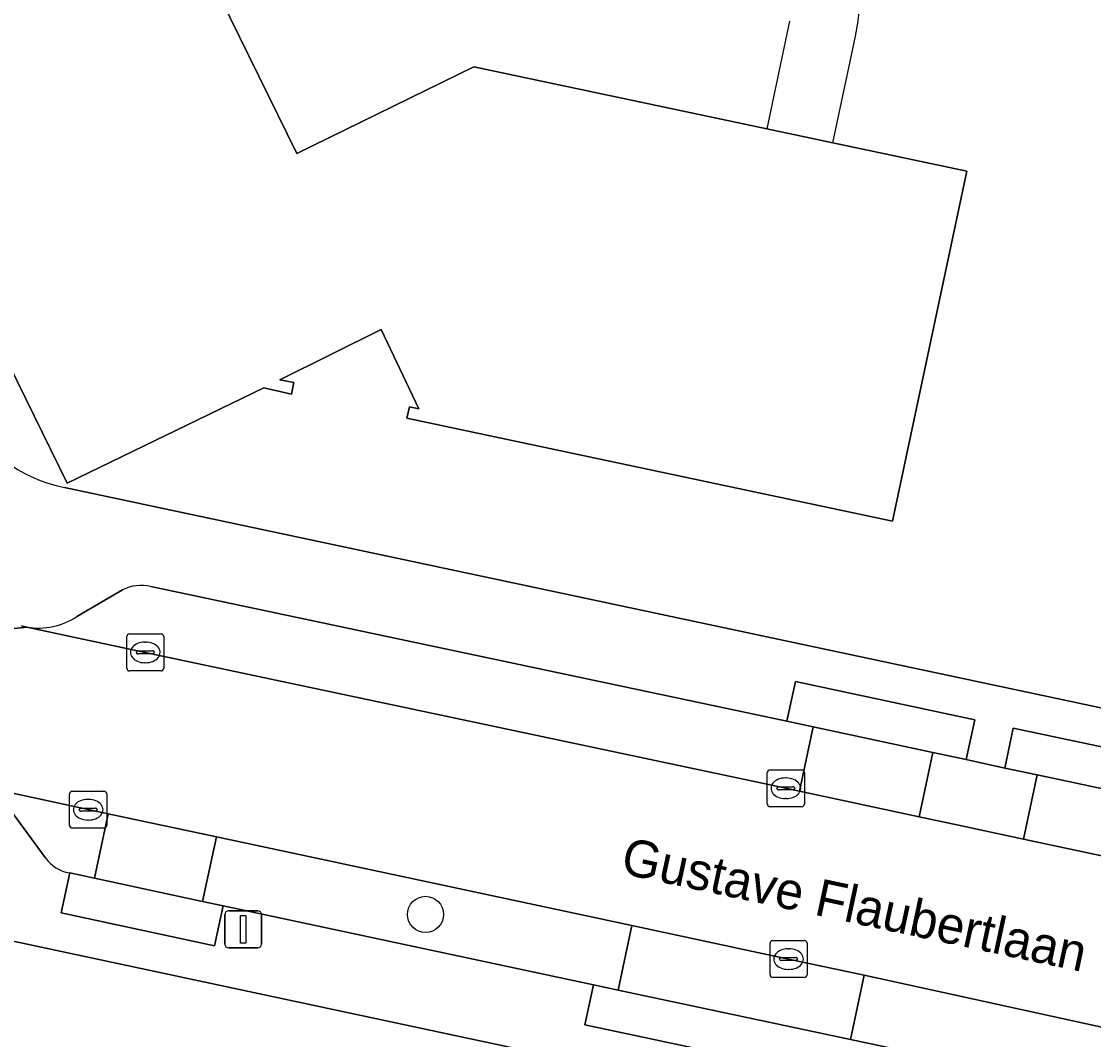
# Model space of a CAD drawing. Extents: x 160455 to 162082, y 388339 to 389736.
# Drawn here: x 160758.44 to 160787.43, y 389012.07 to 389039.61 of the extents above; entities that cross this region are included whole.
import ezdxf

# ---------------------------------------------------------------- set-up
doc = ezdxf.new("R2010")
doc.units = 0
for name, color, linetype in [('IMGEO_Boom', 7, 'Continuous'), ('IMGEO_Erf', 7, 'Continuous'), ('IMGEO_Kolk', 7, 'Continuous'), ('IMGEO_Lichtmast', 7, 'Continuous'), ('IMGEO_Openbare_ruimte_label', 7, 'Continuous'), ('IMGEO_Pand', 7, 'Continuous'), ('IMGEO_Pand_overbouw', 7, 'Continuous'), ('IMGEO_Parkeervlak_open', 7, 'Continuous'), ('IMGEO_Rijbaan_lokaal_gesloten', 7, 'Continuous'), ('IMGEO_Voetpad_open', 7, 'Continuous')]:
    doc.layers.add(name, color=color, linetype=linetype)

msp = doc.modelspace()

# ---------------------------------------------------------------- linework, layer by layer
at = {"layer": 'IMGEO_Boom'}
msp.add_circle((160769.368, 389015.453), 0.489, dxfattribs=at)
at = {"layer": 'IMGEO_Erf'}
for points in [[(160762.799, 389042.336), (160765.888, 389036.033), (160770.678, 389038.374), (160778.592, 389036.698), (160780.379, 389036.32), (160783.999, 389035.553), (160781.995, 389026.092), (160768.864, 389028.873), (160768.937, 389029.183), (160769.19, 389029.124), (160768.172, 389031.272), (160765.432, 389029.914), (160765.805, 389029.841), (160765.743, 389029.525), (160765, 389029.692), (160759.677, 389027.119), (160750.279, 389046.295)], [(160759.604, 389027.003), (160851.028, 389007.553), (160853.401, 389018.708), (160853.658, 389018.653), (160854.144, 389020.941), (160857.076, 389020.317), (160856.589, 389018.03), (160856.015, 389015.332), (160857.131, 389015.095), (160855.333, 389006.643), (160876.381, 389002.172), (160884.301, 389000.512)], [(160816.292, 389002.325), (160756.984, 389014.991)]]:
    msp.add_lwpolyline(points, dxfattribs=at)
msp.add_arc((160760.329, 389030.768), 3.835, 205.0795, 259.1013, dxfattribs=at)
at = {"layer": 'IMGEO_Kolk'}
for p, q in [((160761.291, 389022.113), (160761.291, 389022.965)), ((160761.366, 389023.039), (160762.218, 389023.039)), ((160762.292, 389022.965), (160762.292, 389022.113)), ((160761.55, 389022.533), (160761.55, 389022.545)), ((160761.593, 389022.582), (160761.991, 389022.582)), ((160761.779, 389022.819), (160761.804, 389022.819)), ((160762.034, 389022.545), (160762.034, 389022.533)), ((160761.988, 389022.496), (160761.59, 389022.496)), ((160761.802, 389022.259), (160761.777, 389022.259)), ((160762.218, 389022.039), (160761.366, 389022.039)), ((160778.683, 389019.363), (160779.535, 389019.363)), ((160778.608, 389018.437), (160778.608, 389019.289)), ((160779.096, 389019.143), (160779.121, 389019.143)), ((160779.609, 389019.289), (160779.609, 389018.437)), ((160759.822, 389018.785), (160760.674, 389018.785)), ((160778.867, 389018.857), (160778.867, 389018.869)), ((160779.305, 389018.82), (160778.907, 389018.82)), ((160778.91, 389018.906), (160779.308, 389018.906)), ((160779.351, 389018.869), (160779.351, 389018.857)), ((160759.747, 389017.859), (160759.747, 389018.711)), ((160760.235, 389018.565), (160760.26, 389018.565)), ((160760.748, 389018.711), (160760.748, 389017.859)), ((160779.119, 389018.583), (160779.094, 389018.583)), ((160760.006, 389018.279), (160760.006, 389018.291)), ((160760.444, 389018.242), (160760.046, 389018.242)), ((160760.049, 389018.328), (160760.447, 389018.328)), ((160760.49, 389018.291), (160760.49, 389018.279)), ((160779.535, 389018.363), (160778.683, 389018.363)), ((160760.258, 389018.005), (160760.233, 389018.005)), ((160760.674, 389017.785), (160759.822, 389017.785)), ((160778.756, 389014.745), (160779.608, 389014.745)), ((160778.681, 389013.819), (160778.681, 389014.671)), ((160779.169, 389014.525), (160779.194, 389014.525)), ((160779.682, 389014.671), (160779.682, 389013.819)), ((160778.94, 389014.239), (160778.94, 389014.251)), ((160779.378, 389014.202), (160778.98, 389014.202)), ((160778.983, 389014.288), (160779.381, 389014.288)), ((160779.424, 389014.251), (160779.424, 389014.239)), ((160779.192, 389013.965), (160779.167, 389013.965)), ((160779.608, 389013.745), (160778.756, 389013.745))]:
    msp.add_line(p, q, dxfattribs=at)
for points in [[(160761.291, 389022.113), (160761.291, 389022.965)], [(160761.366, 389023.039), (160762.218, 389023.039)], [(160762.292, 389022.965), (160762.292, 389022.113)], [(160762.218, 389022.039), (160761.366, 389022.039)], [(160778.683, 389019.363), (160779.535, 389019.363)], [(160778.608, 389018.437), (160778.608, 389019.289)], [(160779.609, 389019.289), (160779.609, 389018.437)], [(160759.822, 389018.785), (160760.674, 389018.785)], [(160759.747, 389017.859), (160759.747, 389018.711)], [(160760.748, 389018.711), (160760.748, 389017.859)], [(160779.535, 389018.363), (160778.683, 389018.363)], [(160760.674, 389017.785), (160759.822, 389017.785)], [(160778.756, 389014.745), (160779.608, 389014.745)], [(160778.681, 389013.819), (160778.681, 389014.671)], [(160779.682, 389014.671), (160779.682, 389013.819)], [(160779.608, 389013.745), (160778.756, 389013.745)]]:
    msp.add_lwpolyline(points, dxfattribs=at)
for centre, radius, start, end in [((160761.368, 389022.963), 0.0765, 91.552, 178.448), ((160761.368, 389022.963), 0.0765, 91.552, 178.448), ((160762.216, 389022.963), 0.0765, 1.552, 88.448), ((160762.216, 389022.963), 0.0765, 1.552, 88.448), ((160761.59, 389022.542), 0.0403, 85.8775, 175.7526), ((160761.587, 389022.532), 0.0366, 178.938, 274.7102), ((160761.991, 389022.539), 0.043, 264.8664, 352.4533), ((160761.995, 389022.544), 0.0386, 1.7309, 96.639), ((160761.368, 389022.115), 0.0765, 181.552, 268.448), ((160761.368, 389022.115), 0.0765, 181.552, 268.448), ((160762.216, 389022.115), 0.0765, 271.552, 358.448), ((160762.216, 389022.115), 0.0765, 271.552, 358.448), ((160778.685, 389019.287), 0.0765, 91.552, 178.448), ((160778.685, 389019.287), 0.0765, 91.552, 178.448), ((160779.533, 389019.287), 0.0765, 1.552, 88.448), ((160779.533, 389019.287), 0.0765, 1.552, 88.448), ((160759.824, 389018.709), 0.0765, 91.552, 178.448), ((160759.824, 389018.709), 0.0765, 91.552, 178.448), ((160760.672, 389018.709), 0.0765, 1.552, 88.448), ((160760.672, 389018.709), 0.0765, 1.552, 88.448), ((160778.907, 389018.866), 0.0403, 85.8775, 175.7526), ((160778.904, 389018.856), 0.0366, 178.938, 274.7102), ((160779.308, 389018.863), 0.043, 264.8664, 352.4533), ((160779.312, 389018.868), 0.0386, 1.7309, 96.639), ((160760.046, 389018.288), 0.0403, 85.8775, 175.7526), ((160760.043, 389018.278), 0.0366, 178.938, 274.7102), ((160760.447, 389018.285), 0.043, 264.8664, 352.4533), ((160760.451, 389018.29), 0.0386, 1.7309, 96.639), ((160778.685, 389018.439), 0.0765, 181.552, 268.448), ((160778.685, 389018.439), 0.0765, 181.552, 268.448), ((160779.533, 389018.439), 0.0765, 271.552, 358.448), ((160779.533, 389018.439), 0.0765, 271.552, 358.448), ((160759.824, 389017.861), 0.0765, 181.552, 268.448), ((160759.824, 389017.861), 0.0765, 181.552, 268.448), ((160760.672, 389017.861), 0.0765, 271.552, 358.448), ((160760.672, 389017.861), 0.0765, 271.552, 358.448), ((160778.758, 389014.669), 0.0765, 91.552, 178.448), ((160778.758, 389014.669), 0.0765, 91.552, 178.448), ((160779.606, 389014.669), 0.0765, 1.552, 88.448), ((160779.606, 389014.669), 0.0765, 1.552, 88.448), ((160778.98, 389014.248), 0.0403, 85.8775, 175.7526), ((160778.977, 389014.238), 0.0366, 178.938, 274.7102), ((160779.381, 389014.245), 0.043, 264.8664, 352.4533), ((160779.385, 389014.25), 0.0386, 1.7309, 96.639), ((160778.758, 389013.821), 0.0765, 181.552, 268.448), ((160778.758, 389013.821), 0.0765, 181.552, 268.448), ((160779.606, 389013.821), 0.0765, 271.552, 358.448), ((160779.606, 389013.821), 0.0765, 271.552, 358.448)]:
    msp.add_arc(centre, radius, start, end, dxfattribs=at)
for centre, major_axis, ratio, start_param, end_param in [((160761.778, 389022.539), (-0.387, 0.002), 0.722429, 4.712389, 7.853982), ((160761.803, 389022.539), (-0.39, 0.002), 0.717154, 1.570796, 4.712389), ((160779.095, 389018.863), (-0.387, 0.002), 0.722429, 4.712389, 7.853982), ((160779.12, 389018.863), (-0.39, 0.002), 0.717154, 1.570796, 4.712389), ((160760.234, 389018.285), (-0.387, 0.002), 0.722429, 4.712389, 7.853982), ((160760.259, 389018.285), (-0.39, 0.002), 0.717154, 1.570796, 4.712389), ((160779.168, 389014.245), (-0.387, 0.002), 0.722429, 4.712389, 7.853982), ((160779.193, 389014.245), (-0.39, 0.002), 0.717154, 1.570796, 4.712389)]:
    msp.add_ellipse(centre, major_axis=major_axis, ratio=ratio, start_param=start_param, end_param=end_param, dxfattribs=at)
at = {"layer": 'IMGEO_Lichtmast'}
for p, q in [((160763.944, 389014.647), (160763.944, 389015.447)), ((160763.944, 389015.447), (160763.944, 389014.647)), ((160764.044, 389015.547), (160764.834, 389015.547)), ((160764.834, 389015.547), (160764.044, 389015.547)), ((160764.934, 389015.447), (160764.934, 389014.647)), ((160764.934, 389014.647), (160764.934, 389015.447)), ((160764.834, 389014.547), (160764.044, 389014.547)), ((160764.044, 389014.547), (160764.834, 389014.547))]:
    msp.add_line(p, q, dxfattribs=at)
msp.add_lwpolyline([(160764.364, 389015.422), (160764.514, 389015.422), (160764.514, 389014.672), (160764.364, 389014.672), (160764.364, 389015.422)], dxfattribs=at)
for centre, start, end in [((160764.044, 389015.447), 90, 180), ((160764.044, 389015.447), 90, 180), ((160764.834, 389015.447), 0, 90), ((160764.834, 389015.447), 360, 90), ((160764.044, 389014.647), 180, 270), ((160764.044, 389014.647), 180, 270), ((160764.834, 389014.647), 270, 0), ((160764.834, 389014.647), 270, 0)]:
    msp.add_arc(centre, 0.1, start, end, dxfattribs=at)
at = {"layer": 'IMGEO_Pand'}
msp.add_lwpolyline([(160750.279, 389046.295), (160759.677, 389027.119), (160765, 389029.692), (160765.743, 389029.525), (160765.805, 389029.841), (160765.432, 389029.914), (160768.172, 389031.272), (160769.19, 389029.124), (160768.937, 389029.183), (160768.864, 389028.873), (160781.995, 389026.092), (160783.999, 389035.553), (160780.379, 389036.32), (160778.592, 389036.698), (160770.678, 389038.374), (160765.888, 389036.033), (160762.799, 389042.336)], dxfattribs=at)
at = {"layer": 'IMGEO_Pand_overbouw'}
msp.add_lwpolyline([(160779.209, 389039.611), (160778.592, 389036.698), (160780.379, 389036.32), (160780.845, 389038.517), (160780.922, 389038.862), (160780.991, 389039.21), (160781.052, 389039.561), (160781.104, 389039.915)], dxfattribs=at)
at = {"layer": 'IMGEO_Parkeervlak_open'}
for points in [[(160779.847, 389020.527), (160779.135, 389020.68), (160761.939, 389024.325)], [(160761.174, 389024.231), (160759.955, 389023.517)], [(160758.586, 389023.226), (160761.792, 389022.538), (160779.109, 389018.863), (160779.475, 389018.785), (160779.847, 389020.527)], [(160760.788, 389018.172), (160760.248, 389018.287), (160757.489, 389018.881), (160757.952, 389018.546), (160759.089, 389016.995)], [(160759.748, 389016.574), (160760.416, 389016.43), (160760.788, 389018.172)]]:
    msp.add_lwpolyline(points, dxfattribs=at)
for points in [[(160783.083, 389019.832), (160779.847, 389020.527), (160779.475, 389018.785), (160782.712, 389018.094)], [(160785.9, 389019.227), (160785.028, 389019.411), (160783.984, 389019.639), (160783.083, 389019.832), (160782.712, 389018.094), (160783.776, 389017.867), (160785.529, 389017.492)], [(160788.953, 389018.581), (160785.9, 389019.227), (160785.529, 389017.492), (160788.58, 389016.839)], [(160763.714, 389017.547), (160760.788, 389018.172), (160760.416, 389016.43), (160763.341, 389015.799)], [(160763.714, 389017.547), (160763.341, 389015.799), (160763.895, 389015.68), (160773.907, 389013.545), (160774.577, 389013.403), (160774.949, 389015.15)], [(160779.183, 389014.246), (160774.949, 389015.15), (160774.577, 389013.403), (160780.857, 389012.068), (160781.228, 389013.811)], [(160781.228, 389013.811), (160780.857, 389012.068), (160781.877, 389011.851), (160791.615, 389009.774), (160792.23, 389009.642), (160792.588, 389011.325)]]:
    msp.add_lwpolyline(points, close=True, dxfattribs=at)
for centre, radius, start, end in [((160761.689, 389023.203), 1.149, 77.4115, 116.5988), ((160758.909, 389025.072), 1.874, 260.0787, 303.9221), ((160759.881, 389017.509), 0.944, 212.9682, 261.8871)]:
    msp.add_arc(centre, radius, start, end, dxfattribs=at)
at = {"layer": 'IMGEO_Rijbaan_lokaal_gesloten'}
for points in [[(160788.58, 389016.839), (160785.529, 389017.492), (160783.776, 389017.867), (160782.712, 389018.094), (160779.475, 389018.785), (160779.109, 389018.863), (160761.792, 389022.538), (160758.586, 389023.226), (160757.046, 389023.061), (160754.132, 389022.796), (160751.462, 389022.309), (160749.244, 389021.595), (160747.023, 389020.598), (160743.89, 389018.927), (160743.686, 389018.833), (160734.25, 389014.251)], [(160743.89, 389018.927), (160747.023, 389020.598), (160749.244, 389021.595), (160751.462, 389022.309), (160754.132, 389022.796), (160757.046, 389023.061), (160758.586, 389023.226), (160758.444, 389023.256)], [(160755.172, 389019.027), (160755.282, 389019.047), (160755.435, 389019.076), (160755.703, 389019.088), (160757.283, 389018.925), (160757.489, 389018.881), (160760.248, 389018.287), (160760.788, 389018.172), (160763.714, 389017.547), (160774.949, 389015.15), (160779.183, 389014.246), (160781.228, 389013.811), (160792.588, 389011.325)]]:
    msp.add_lwpolyline(points, dxfattribs=at)
at = {"layer": 'IMGEO_Voetpad_open'}
for points in [[(160855.333, 389006.643), (160854.217, 389006.879), (160851.028, 389007.553), (160759.604, 389027.003)], [(160761.939, 389024.325), (160779.135, 389020.68), (160779.366, 389021.755), (160784.215, 389020.714), (160783.984, 389019.639), (160785.028, 389019.411), (160785.256, 389020.487), (160789.993, 389019.485), (160789.765, 389018.409), (160799.2, 389016.413), (160799.304, 389016.901), (160806.98, 389015.253), (160806.876, 389014.765), (160814.475, 389013.157), (160816.553, 389012.731), (160828.933, 389010.089), (160844.001, 389006.893), (160845.862, 389006.495), (160849.419, 389005.735), (160849.523, 389006.223), (160854.547, 389005.149), (160854.443, 389004.661), (160876.487, 389000), (160887.539, 388997.663)], [(160759.955, 389023.517), (160761.174, 389024.231)], [(160758.444, 389023.256), (160758.586, 389023.226)], [(160759.089, 389016.995), (160757.952, 389018.546), (160757.489, 389018.881), (160757.283, 389018.925), (160755.703, 389019.088), (160755.435, 389019.076), (160755.282, 389019.047), (160755.172, 389019.027)], [(160814.226, 389005.773), (160814.025, 389005.016), (160813.758, 389005.045), (160813.653, 389004.557), (160808.611, 389005.646), (160808.716, 389006.134), (160799.298, 389008.123), (160799.067, 389007.048), (160791.384, 389008.699), (160791.615, 389009.774), (160781.877, 389011.851), (160781.648, 389010.775), (160773.678, 389012.469), (160773.907, 389013.545), (160763.895, 389015.68), (160763.663, 389014.605), (160759.516, 389015.499), (160759.748, 389016.574)], [(160756.984, 389014.991), (160816.292, 389002.325), (160826.345, 389000.901)]]:
    msp.add_lwpolyline(points, dxfattribs=at)
for points in [[(160779.366, 389021.755), (160779.135, 389020.68), (160779.847, 389020.527), (160783.083, 389019.832), (160783.984, 389019.639), (160784.215, 389020.714)], [(160789.993, 389019.485), (160785.256, 389020.487), (160785.028, 389019.411), (160785.9, 389019.227), (160788.953, 389018.581), (160789.765, 389018.409)], [(160763.895, 389015.68), (160763.341, 389015.799), (160760.416, 389016.43), (160759.748, 389016.574), (160759.516, 389015.499), (160763.663, 389014.605)], [(160774.577, 389013.403), (160773.907, 389013.545), (160773.678, 389012.469), (160781.648, 389010.775), (160781.877, 389011.851), (160780.857, 389012.068)]]:
    msp.add_lwpolyline(points, close=True, dxfattribs=at)
for centre, radius, start, end in [((160760.329, 389030.768), 3.835, 205.0795, 259.1013), ((160761.689, 389023.203), 1.149, 77.4115, 116.5988), ((160758.909, 389025.072), 1.874, 260.0787, 303.9221), ((160759.881, 389017.509), 0.944, 212.9682, 261.8871)]:
    msp.add_arc(centre, radius, start, end, dxfattribs=at)

# ---------------------------------------------------------------- texts
at = {"layer": 'IMGEO_Openbare_ruimte_label'}
msp.add_text('Gustave Flaubertlaan', height=1, rotation=347.9373, dxfattribs=at).set_placement((160774.61, 389016.568))

doc.saveas('drawing.dxf')
